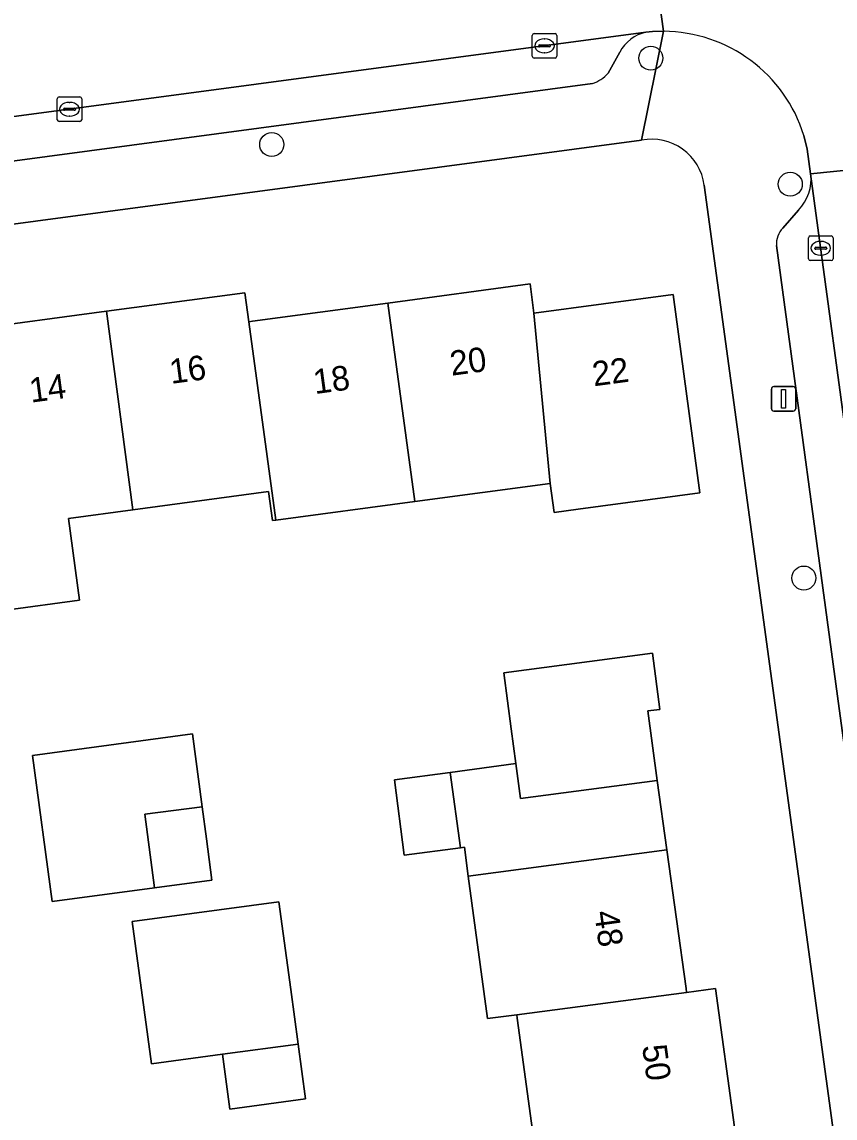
# Model space of a CAD drawing. Extents: x 163426 to 164192, y 380329 to 381641.
# Drawn here: x 163563.29 to 163596.37, y 381054.66 to 381099.27 of the extents above; entities that cross this region are included whole.
import ezdxf

# ---------------------------------------------------------------- set-up
doc = ezdxf.new("R2010")
doc.units = 0
for name, color, linetype in [('IMGEO_Boom', 7, 'Continuous'), ('IMGEO_Erf', 7, 'Continuous'), ('IMGEO_Kolk', 7, 'Continuous'), ('IMGEO_Lichtmast', 7, 'Continuous'), ('IMGEO_Pand', 7, 'Continuous'), ('IMGEO_Pand_nummerreeks', 7, 'Continuous'), ('IMGEO_Parkeervlak_open', 7, 'Continuous'), ('IMGEO_Rijbaan_lokaal_open', 7, 'Continuous'), ('IMGEO_Voetpad_open', 7, 'Continuous')]:
    doc.layers.add(name, color=color, linetype=linetype)

msp = doc.modelspace()

# ---------------------------------------------------------------- linework, layer by layer
at = {"layer": 'IMGEO_Boom'}
for centre in [(163588.876, 381097.796), (163573.451, 381094.282), (163594.55, 381092.667), (163595.102, 381076.637)]:
    msp.add_circle(centre, 0.489, dxfattribs=at)
at = {"layer": 'IMGEO_Erf'}
for points in [[(163588.503, 381094.461), (163544.642, 381088.602)], [(163604.031, 380997.461), (163603.685, 381000), (163591.052, 381092.633)], [(163561.087, 381086.74), (163566.722, 381087.495), (163572.362, 381088.251), (163572.523, 381087.07), (163572.67, 381087.09), (163578.18, 381087.831), (163583.97, 381088.61), (163584.11, 381087.42), (163589.78, 381088.18), (163590.87, 381080.1), (163585.915, 381079.434), (163584.937, 381079.303), (163584.777, 381080.491), (163579.277, 381079.752), (163573.624, 381078.992), (163573.486, 381078.973), (163573.326, 381080.162), (163567.805, 381079.42), (163565.178, 381079.067), (163565.625, 381075.731), (163562.633, 381075.328)], [(163584.188, 381053.249), (163583.444, 381058.729), (163583.426, 381058.863), (163582.237, 381058.706), (163581.45, 381064.499), (163581.292, 381065.681), (163581.13, 381065.66), (163578.84, 381065.36), (163578.44, 381068.42), (163580.716, 381068.727), (163583.382, 381069.082), (163583.197, 381070.502), (163582.9, 381072.78), (163588.94, 381073.58), (163589.24, 381071.29), (163588.75, 381071.226), (163589.14, 381068.402), (163589.53, 381065.58), (163590.31, 381059.93), (163590.332, 381059.774), (163591.509, 381059.929), (163592.279, 381054.293)]]:
    msp.add_lwpolyline(points, dxfattribs=at)
for points in [[(163568.686, 381064.033), (163564.514, 381063.474), (163563.717, 381069.421), (163570.224, 381070.292), (163570.619, 381067.327), (163570.794, 381066.018), (163571.017, 381064.345)], [(163571.449, 381057.255), (163568.556, 381056.866), (163567.777, 381062.661), (163573.742, 381063.463), (163574.222, 381059.893), (163574.521, 381057.668), (163574.822, 381055.433), (163571.75, 381055.02)]]:
    msp.add_lwpolyline(points, close=True, dxfattribs=at)
msp.add_arc((163588.904, 381092.329), 2.17, 8.0615, 100.6466, dxfattribs=at)
at = {"layer": 'IMGEO_Kolk'}
for p, q in [((163584.051, 381097.873), (163584.051, 381098.725)), ((163584.126, 381098.799), (163584.978, 381098.799)), ((163585.052, 381098.725), (163585.052, 381097.873)), ((163584.31, 381098.293), (163584.31, 381098.305)), ((163584.353, 381098.342), (163584.751, 381098.342)), ((163584.539, 381098.579), (163584.564, 381098.579)), ((163584.794, 381098.305), (163584.794, 381098.293)), ((163584.748, 381098.256), (163584.35, 381098.256)), ((163584.562, 381098.019), (163584.537, 381098.019)), ((163584.978, 381097.799), (163584.126, 381097.799)), ((163564.722, 381095.293), (163564.722, 381096.145)), ((163564.797, 381096.219), (163565.649, 381096.219)), ((163565.723, 381096.145), (163565.723, 381095.293)), ((163564.981, 381095.713), (163564.981, 381095.725)), ((163565.419, 381095.676), (163565.021, 381095.676)), ((163565.024, 381095.762), (163565.422, 381095.762)), ((163565.21, 381095.999), (163565.235, 381095.999)), ((163565.465, 381095.725), (163565.465, 381095.713)), ((163565.649, 381095.219), (163564.797, 381095.219)), ((163565.233, 381095.439), (163565.208, 381095.439)), ((163595.29, 381089.634), (163595.29, 381090.486)), ((163595.365, 381090.56), (163596.217, 381090.56)), ((163595.778, 381090.34), (163595.803, 381090.34)), ((163596.291, 381090.486), (163596.291, 381089.634)), ((163595.549, 381090.054), (163595.549, 381090.066)), ((163595.987, 381090.017), (163595.589, 381090.017)), ((163595.592, 381090.103), (163595.99, 381090.103)), ((163596.033, 381090.066), (163596.033, 381090.054)), ((163596.217, 381089.56), (163595.365, 381089.56)), ((163595.801, 381089.78), (163595.776, 381089.78))]:
    msp.add_line(p, q, dxfattribs=at)
for points in [[(163584.051, 381097.873), (163584.051, 381098.725)], [(163584.126, 381098.799), (163584.978, 381098.799)], [(163585.052, 381098.725), (163585.052, 381097.873)], [(163584.978, 381097.799), (163584.126, 381097.799)], [(163564.722, 381095.293), (163564.722, 381096.145)], [(163564.797, 381096.219), (163565.649, 381096.219)], [(163565.723, 381096.145), (163565.723, 381095.293)], [(163565.649, 381095.219), (163564.797, 381095.219)], [(163595.29, 381089.634), (163595.29, 381090.486)], [(163595.365, 381090.56), (163596.217, 381090.56)], [(163596.291, 381090.486), (163596.291, 381089.634)], [(163596.217, 381089.56), (163595.365, 381089.56)]]:
    msp.add_lwpolyline(points, dxfattribs=at)
for centre, radius, start, end in [((163584.128, 381098.723), 0.0765, 91.552, 178.448), ((163584.128, 381098.723), 0.0765, 91.552, 178.448), ((163584.976, 381098.723), 0.0765, 1.552, 88.448), ((163584.976, 381098.723), 0.0765, 1.552, 88.448), ((163584.35, 381098.302), 0.0403, 85.8775, 175.7526), ((163584.347, 381098.292), 0.0366, 178.938, 274.7102), ((163584.751, 381098.299), 0.043, 264.8664, 352.4533), ((163584.755, 381098.304), 0.0386, 1.7309, 96.639), ((163584.128, 381097.875), 0.0765, 181.552, 268.448), ((163584.128, 381097.875), 0.0765, 181.552, 268.448), ((163584.976, 381097.875), 0.0765, 271.552, 358.448), ((163584.976, 381097.875), 0.0765, 271.552, 358.448), ((163564.799, 381096.143), 0.0765, 91.552, 178.448), ((163564.799, 381096.143), 0.0765, 91.552, 178.448), ((163565.647, 381096.143), 0.0765, 1.552, 88.448), ((163565.647, 381096.143), 0.0765, 1.552, 88.448), ((163565.021, 381095.722), 0.0403, 85.8775, 175.7526), ((163565.018, 381095.712), 0.0366, 178.938, 274.7102), ((163565.422, 381095.719), 0.043, 264.8664, 352.4533), ((163565.426, 381095.724), 0.0386, 1.7309, 96.639), ((163564.799, 381095.295), 0.0765, 181.552, 268.448), ((163564.799, 381095.295), 0.0765, 181.552, 268.448), ((163565.647, 381095.295), 0.0765, 271.552, 358.448), ((163565.647, 381095.295), 0.0765, 271.552, 358.448), ((163595.367, 381090.484), 0.0765, 91.552, 178.448), ((163595.367, 381090.484), 0.0765, 91.552, 178.448), ((163596.215, 381090.484), 0.0765, 1.552, 88.448), ((163596.215, 381090.484), 0.0765, 1.552, 88.448), ((163595.589, 381090.063), 0.0403, 85.8775, 175.7526), ((163595.586, 381090.053), 0.0366, 178.938, 274.7102), ((163595.99, 381090.06), 0.043, 264.8664, 352.4533), ((163595.994, 381090.065), 0.0386, 1.7309, 96.639), ((163595.367, 381089.636), 0.0765, 181.552, 268.448), ((163595.367, 381089.636), 0.0765, 181.552, 268.448), ((163596.215, 381089.636), 0.0765, 271.552, 358.448), ((163596.215, 381089.636), 0.0765, 271.552, 358.448)]:
    msp.add_arc(centre, radius, start, end, dxfattribs=at)
for centre, major_axis, ratio, start_param, end_param in [((163584.538, 381098.299), (-0.387, 0.002), 0.722429, 4.712389, 7.853982), ((163584.563, 381098.299), (-0.39, 0.002), 0.717154, 1.570796, 4.712389), ((163565.209, 381095.719), (-0.387, 0.002), 0.722429, 4.712389, 7.853982), ((163565.234, 381095.719), (-0.39, 0.002), 0.717154, 1.570796, 4.712389), ((163595.777, 381090.06), (-0.387, 0.002), 0.722429, 4.712389, 7.853982), ((163595.802, 381090.06), (-0.39, 0.002), 0.717154, 1.570796, 4.712389)]:
    msp.add_ellipse(centre, major_axis=major_axis, ratio=ratio, start_param=start_param, end_param=end_param, dxfattribs=at)
at = {"layer": 'IMGEO_Lichtmast'}
for p, q in [((163593.78, 381083.531), (163593.78, 381084.331)), ((163593.78, 381084.331), (163593.78, 381083.531)), ((163593.88, 381084.431), (163594.67, 381084.431)), ((163594.67, 381084.431), (163593.88, 381084.431)), ((163594.77, 381084.331), (163594.77, 381083.531)), ((163594.77, 381083.531), (163594.77, 381084.331)), ((163594.67, 381083.431), (163593.88, 381083.431)), ((163593.88, 381083.431), (163594.67, 381083.431))]:
    msp.add_line(p, q, dxfattribs=at)
msp.add_lwpolyline([(163594.2, 381084.306), (163594.35, 381084.306), (163594.35, 381083.556), (163594.2, 381083.556), (163594.2, 381084.306)], dxfattribs=at)
for centre, start, end in [((163593.88, 381084.331), 90, 180), ((163593.88, 381084.331), 90, 180), ((163594.67, 381084.331), 0, 90), ((163594.67, 381084.331), 360, 90), ((163593.88, 381083.531), 180, 270), ((163593.88, 381083.531), 180, 270), ((163594.67, 381083.531), 270, 0), ((163594.67, 381083.531), 270, 0)]:
    msp.add_arc(centre, 0.1, start, end, dxfattribs=at)
at = {"layer": 'IMGEO_Pand'}
for points in [[(163584.11, 381087.42), (163583.97, 381088.61), (163578.18, 381087.831), (163579.277, 381079.752), (163584.777, 381080.491)], [(163572.523, 381087.07), (163572.362, 381088.251), (163566.722, 381087.495), (163567.805, 381079.42), (163573.326, 381080.162), (163573.486, 381078.973), (163573.624, 381078.992)], [(163584.11, 381087.42), (163584.777, 381080.491), (163584.937, 381079.303), (163585.915, 381079.434), (163590.87, 381080.1), (163589.78, 381088.18)], [(163578.18, 381087.831), (163572.67, 381087.09), (163572.523, 381087.07), (163573.624, 381078.992), (163579.277, 381079.752)], [(163561.087, 381086.74), (163562.191, 381078.666), (163562.633, 381075.328), (163565.625, 381075.731), (163565.178, 381079.067), (163567.805, 381079.42), (163566.722, 381087.495)], [(163588.75, 381071.226), (163589.24, 381071.29), (163588.94, 381073.58), (163582.9, 381072.78), (163583.197, 381070.502), (163583.382, 381069.082), (163583.567, 381067.663), (163589.14, 381068.402)], [(163570.619, 381067.327), (163570.224, 381070.292), (163563.717, 381069.421), (163564.514, 381063.474), (163568.686, 381064.033), (163568.285, 381067.022)], [(163589.14, 381068.402), (163583.567, 381067.663), (163583.382, 381069.082), (163580.716, 381068.727), (163581.13, 381065.66), (163581.292, 381065.681), (163581.45, 381064.499), (163589.53, 381065.58)], [(163578.84, 381065.36), (163581.13, 381065.66), (163580.716, 381068.727), (163578.44, 381068.42)], [(163570.619, 381067.327), (163568.285, 381067.022), (163568.686, 381064.033), (163571.017, 381064.345), (163570.794, 381066.018)], [(163589.53, 381065.58), (163581.45, 381064.499), (163582.237, 381058.706), (163583.426, 381058.863), (163590.332, 381059.774), (163590.31, 381059.93)], [(163567.777, 381062.661), (163568.556, 381056.866), (163571.449, 381057.255), (163574.521, 381057.668), (163574.222, 381059.893), (163573.742, 381063.463)], [(163591.509, 381059.929), (163590.332, 381059.774), (163583.426, 381058.863), (163583.444, 381058.729), (163584.188, 381053.249), (163592.279, 381054.293)], [(163571.449, 381057.255), (163571.75, 381055.02), (163574.822, 381055.433), (163574.521, 381057.668)]]:
    msp.add_lwpolyline(points, close=True, dxfattribs=at)
at = {"layer": 'IMGEO_Parkeervlak_open'}
for points in [[(163588.678, 381098.851), (163540.896, 381092.473)], [(163587.134, 381097.186), (163587.61, 381098.047)], [(163543.832, 381091.056), (163586.498, 381096.765)], [(163607.888, 381000.887), (163595.38, 381093.094)], [(163594.89, 381091.616), (163594.243, 381090.88)], [(163593.989, 381090.174), (163596.472, 381071.828), (163597.185, 381066.558), (163602.552, 381026.894), (163603.261, 381021.656), (163605.735, 381003.371)]]:
    msp.add_lwpolyline(points, dxfattribs=at)
for centre, radius, start, end in [((163589.027, 381097.276), 1.613, 102.4931, 151.4524), ((163586.063, 381098.114), 1.417, 287.8906, 319.1145), ((163593.564, 381092.876), 1.83, 316.4725, 6.8438), ((163594.92, 381090.238), 0.933, 136.4961, 183.9291)]:
    msp.add_arc(centre, radius, start, end, dxfattribs=at)
at = {"layer": 'IMGEO_Rijbaan_lokaal_open'}
for points in [[(163589.2, 381104.11), (163588.68, 381103.951), (163589.386, 381098.89)], [(163588.678, 381098.851), (163588.947, 381098.887), (163589.386, 381098.89), (163588.68, 381103.951), (163588.22, 381103.933), (163540.061, 381097.511)], [(163539.927, 381092.358), (163540.896, 381092.473), (163588.678, 381098.851)], [(163595.104, 381094.65), (163595.241, 381094.091), (163595.38, 381093.094), (163600.456, 381093.608), (163600.309, 381094.615), (163600.307, 381094.989), (163600.306, 381095.362)]]:
    msp.add_lwpolyline(points, dxfattribs=at)
msp.add_lwpolyline([(163608.008, 381000), (163613.059, 381000.578), (163613.016, 381000.89), (163612.89, 381001.887), (163600.456, 381093.608), (163595.38, 381093.094), (163607.888, 381000.887)], close=True, dxfattribs=at)
msp.add_arc((163589.354, 381092.871), 6.019, 17.1879, 89.6969, dxfattribs=at)
at = {"layer": 'IMGEO_Voetpad_open'}
for points in [[(163589.386, 381098.89), (163588.503, 381094.461)], [(163588.503, 381094.461), (163589.386, 381098.89), (163588.947, 381098.887), (163588.678, 381098.851)], [(163587.61, 381098.047), (163587.134, 381097.186)], [(163586.498, 381096.765), (163543.832, 381091.056)], [(163544.642, 381088.602), (163588.503, 381094.461)], [(163595.38, 381093.094), (163595.241, 381094.091), (163595.104, 381094.65)], [(163591.052, 381092.633), (163603.685, 381000), (163604.031, 380997.461)], [(163594.243, 381090.88), (163594.89, 381091.616)], [(163597.185, 381066.558), (163596.472, 381071.828), (163593.989, 381090.174)]]:
    msp.add_lwpolyline(points, dxfattribs=at)
for centre, radius, start, end in [((163589.027, 381097.276), 1.613, 102.4931, 151.4524), ((163589.354, 381092.871), 6.019, 17.1879, 89.6969), ((163586.063, 381098.114), 1.417, 287.8906, 319.1145), ((163588.904, 381092.329), 2.17, 8.0615, 100.6466), ((163593.564, 381092.876), 1.83, 316.4725, 6.8438), ((163594.92, 381090.238), 0.933, 136.4961, 183.9291)]:
    msp.add_arc(centre, radius, start, end, dxfattribs=at)

# ---------------------------------------------------------------- texts
at = {"layer": 'IMGEO_Pand_nummerreeks'}
for s, rotation, p in [('20', 7.6611, (163580.767, 381084.87)), ('16', 7.6375, (163569.357, 381084.538)), ('22', 7.6344, (163586.559, 381084.439)), ('14', 7.6377, (163563.655, 381083.774)), ('18', 7.6604, (163575.207, 381084.122)), ('48', 277.8608, (163586.569, 381063.043)), ('50', 277.7748, (163588.519, 381057.592))]:
    msp.add_text(s, height=1, rotation=rotation, dxfattribs=at).set_placement(p)

doc.saveas('drawing.dxf')
